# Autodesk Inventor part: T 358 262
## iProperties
Created: 2005-10
Part Number: T 358 262
Material: 2.0402
Document SubType Name: Modeling
Designer: I.Baliuc
Manufacturer: Standard
Standards Organization: Custom
Description: Buchse
Density: 8.2 g/cm^3
Title: Buchse
Company: Mayer & Müller AG Schaltgeräte
Author: T.Messerschmitt
Revision Number: 358262
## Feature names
1. Drehung1 [Revolution]
